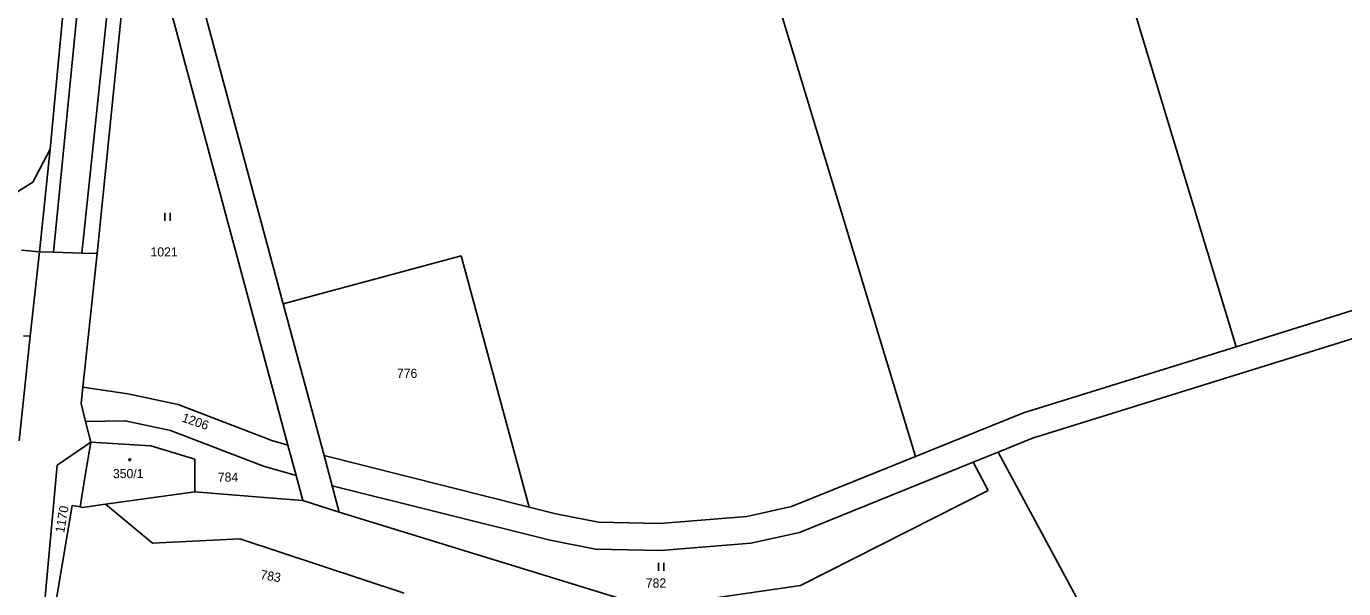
# Model space of a CAD drawing. Extents: x -812394 to -807601, y -1013097 to -1009266.
# Drawn here: x -811005.4 to -810760.5, y -1011227.4 to -1011122.9 of the extents above; entities that cross this region are included whole.
import ezdxf

# ---------------------------------------------------------------- set-up
doc = ezdxf.new("R2010")
doc.units = 0
for name, color, linetype in [('Default', 7, 'Continuous'), ('KN_HRANICE', 7, 'Continuous'), ('KN_KULTURY', 7, 'Continuous'), ('KN_PARCELY', 7, 'Continuous'), ('KN_SLUCKY', 7, 'Continuous')]:
    doc.layers.add(name, color=color, linetype=linetype)

# ---------------------------------------------------------------- blocks, each defined once
blk = doc.blocks.new('306')
at = {"layer": 'Default'}
for p, q in [((-0.5, 1.5), (-0.5, 0)), ((0.5, 0), (0.5, 1.5))]:
    blk.add_line(p, q, dxfattribs=at)
blk = doc.blocks.new('NAHRADNI_SYMBOL')
at = {"layer": 'Default'}
blk.add_lwpolyline([(0.09, 0.15), (0.18, 0), (0.09, -0.15), (-0.09, -0.15), (-0.18, 0), (-0.09, 0.15), (0.09, 0.15)], dxfattribs=at)

msp = doc.modelspace()

# ---------------------------------------------------------------- linework, layer by layer
at = {"layer": 'KN_HRANICE'}
for p, q in [((-810817.55, -1011059.91), (-810780.44, -1011182.42)), ((-810840.09, -1011202.83), (-810877.77, -1011078.41)), ((-810982.45, -1011105.41), (-810956.76, -1011200.71)), ((-810957.61, -1011174.47), (-810974.27, -1011112.67)), ((-810998.22, -1011116.9), (-811000.96, -1011145.71)), ((-810590.61, -1011123.35), (-810780.44, -1011182.42)), ((-811000.96, -1011145.71), (-811004.2, -1011151.86)), ((-811002.95, -1011164.79), (-811000.96, -1011145.71)), ((-811004.2, -1011151.86), (-811011.7, -1011156.55)), ((-811002.95, -1011164.79), (-811006.28, -1011164.5)), ((-811004.64, -1011180.47), (-811002.95, -1011164.79)), ((-811000.33, -1011164.87), (-811002.95, -1011164.79)), ((-810995.05, -1011165.02), (-811000.33, -1011164.87)), ((-810992.21, -1011165.1), (-810995.05, -1011165.02)), ((-810994.88, -1011189.95), (-810992.21, -1011165.1)), ((-810957.61, -1011174.47), (-810924.51, -1011165.55)), ((-810924.51, -1011165.55), (-810911.92, -1011212.23)), ((-810950.02, -1011202.64), (-810957.61, -1011174.47)), ((-810818.33, -1011199.44), (-810741.21, -1011175.44)), ((-811006.73, -1011199.88), (-811004.64, -1011180.47)), ((-811005.89, -1011180.37), (-811004.64, -1011180.47)), ((-810780.44, -1011182.42), (-810820.01, -1011194.73)), ((-810995.21, -1011192.97), (-810994.88, -1011189.95)), ((-810986.52, -1011191.18), (-810994.88, -1011189.95)), ((-810994.36, -1011196.29), (-810995.21, -1011192.97)), ((-810977.14, -1011193.18), (-810986.52, -1011191.18)), ((-810959.71, -1011199.86), (-810977.14, -1011193.18)), ((-810820.01, -1011194.73), (-810840.09, -1011202.83)), ((-810994.36, -1011196.29), (-810987, -1011196.19)), ((-810993.37, -1011200.18), (-810994.36, -1011196.29)), ((-810987, -1011196.19), (-810978.56, -1011197.99)), ((-810978.56, -1011197.99), (-810961.3, -1011204.6)), ((-810999.64, -1011204.43), (-810993.37, -1011200.18)), ((-810982.24, -1011200.82), (-810993.37, -1011200.18)), ((-810956.76, -1011200.71), (-810959.71, -1011199.86)), ((-810824.69, -1011202.01), (-810818.33, -1011199.44)), ((-810974.04, -1011203.29), (-810982.24, -1011200.82)), ((-810955.24, -1011206.35), (-810956.76, -1011200.71)), ((-810950.02, -1011202.64), (-810948.51, -1011208.24)), ((-810911.92, -1011212.23), (-810950.02, -1011202.64)), ((-810840.09, -1011202.83), (-810863.09, -1011212.12)), ((-810829.36, -1011203.9), (-810824.69, -1011202.01)), ((-810806.75, -1011235.18), (-810824.69, -1011202.01)), ((-811002.17, -1011232.3), (-810999.64, -1011204.43)), ((-810974.02, -1011209.41), (-810974.04, -1011203.29)), ((-810961.3, -1011204.6), (-810955.24, -1011206.35)), ((-810861.6, -1011216.92), (-810829.36, -1011203.9)), ((-810829.36, -1011203.9), (-810826.53, -1011209.12)), ((-810953.98, -1011211.02), (-810955.24, -1011206.35)), ((-810990.68, -1011211.7), (-810974.02, -1011209.41)), ((-810961.08, -1011210.45), (-810974.02, -1011209.41)), ((-810947.19, -1011213.16), (-810948.51, -1011208.24)), ((-810948.51, -1011208.24), (-810908.01, -1011218.37)), ((-810826.53, -1011209.12), (-810861.45, -1011226.78)), ((-810995.36, -1011212.19), (-810994.94, -1011212.29)), ((-810994.94, -1011212.29), (-810990.68, -1011211.7)), ((-810990.68, -1011211.7), (-810981.95, -1011218.9)), ((-810953.98, -1011211.02), (-810961.08, -1011210.45)), ((-810947.19, -1011213.16), (-810953.98, -1011211.02)), ((-810906.93, -1011213.49), (-810911.92, -1011212.23)), ((-810863.09, -1011212.12), (-810871.4, -1011213.98)), ((-810889.59, -1011230.84), (-810947.19, -1011213.16)), ((-810899, -1011215.01), (-810906.93, -1011213.49)), ((-810887.58, -1011215.26), (-810899, -1011215.01)), ((-810871.4, -1011213.98), (-810887.58, -1011215.26)), ((-810870.66, -1011218.94), (-810861.6, -1011216.92)), ((-810981.95, -1011218.9), (-810965.7, -1011218.1)), ((-810965.7, -1011218.1), (-810935.11, -1011228.19)), ((-810908.01, -1011218.37), (-810899.53, -1011220)), ((-810899.53, -1011220), (-810887.44, -1011220.26)), ((-810887.44, -1011220.26), (-810870.66, -1011218.94)), ((-810861.45, -1011226.78), (-810889.59, -1011230.84))]:
    msp.add_line(p, q, dxfattribs=at)
for points in [[(-810986.65, -1011105.04), (-810987.39, -1011117.32), (-810992.21, -1011165.1)], [(-810993.37, -1011200.18), (-810994.44, -1011206.32), (-810995.36, -1011212.19)], [(-811000.55, -1011233.96), (-810996.85, -1011211.94), (-810995.36, -1011212.19)]]:
    msp.add_lwpolyline(points, dxfattribs=at)
at = {"layer": 'KN_SLUCKY'}
for points in [[(-811000.33, -1011164.87), (-810995.6, -1011117.04), (-810993.22, -1011089.39), (-810991.44, -1011051.79), (-810989.93, -1011025.95), (-810988.35, -1011012.09), (-810985.51, -1010996.59), (-810982.68, -1010987.06), (-810978.95, -1010979.06), (-810975.35, -1010972.95)], [(-810970.63, -1010976.53), (-810974.13, -1010981.9), (-810977.67, -1010989.22), (-810980.74, -1010998.6), (-810983.37, -1011013.1), (-810984.59, -1011025.93), (-810986.15, -1011052.66), (-810988.17, -1011090.35), (-810990.05, -1011117.32), (-810995.05, -1011165.02)]]:
    msp.add_lwpolyline(points, dxfattribs=at)

# ---------------------------------------------------------------- block references
at = {"layer": 'KN_KULTURY'}
for name, p in [('306', (-810979.13, -1011159.04)), ('NAHRADNI_SYMBOL', (-810986.14, -1011203.43)), ('306', (-810887.37, -1011224.08))]:
    msp.add_blockref(name, p, dxfattribs=at)

# ---------------------------------------------------------------- texts
at = {"layer": 'KN_PARCELY'}
for s, p in [('1021', (-810982.29, -1011165.66)), ('776', (-810936.48, -1011188.22)), ('350/1', (-810989.28, -1011206.84)), ('784', (-810969.78, -1011207.5)), ('782', (-810890.21, -1011227.17))]:
    msp.add_text(s, height=1.7, dxfattribs=at).set_placement(p)
for s, rotation, p in [('1206', 341.139, (-810976.6, -1011196.29)), ('1170', 80.042, (-810998.36, -1011217.11)), ('783', 349.848, (-810961.96, -1011225.53))]:
    msp.add_text(s, height=1.7, rotation=rotation, dxfattribs=at).set_placement(p)

doc.saveas('drawing.dxf')
